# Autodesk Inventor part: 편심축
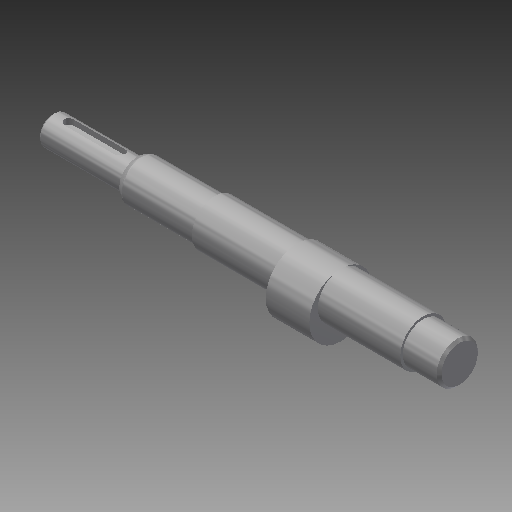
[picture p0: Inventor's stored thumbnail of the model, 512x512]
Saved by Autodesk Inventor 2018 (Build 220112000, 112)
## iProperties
Created: 2017-08
Part Number: 편심축
Material: 강철, 연강
Document SubType Name: Modeling
Designer: mduedu
Density: 1 g/cm^3
Appearance: 강철
Author: mduedu
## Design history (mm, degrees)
sketch "스케치1"
  geometry: L1 (0, 0)-(168, 0); L2 (168, 0)-(168, 8.5); L3 (168, 8.5)-(153, 8.5); L4 (153, 8.5)-(153, 9.5); L5 (153, 9.5)-(67, 9.5); L6 (67, 9.5)-(67, 8.5); L7 (67, 8.5)-(35, 8.5); L8 (35, 8.5)-(35, 6); L9 (35, 6)-(0, 6); L10 (0, 6)-(0, 0)
  constraints: 20 end point, 6 parallel, 2 collinear, 2 perpendicular, 1 horizontal
  dimensions: "d0" = 168 distance of L1.start L1.end; "d1" = 17 diameter of L3 L1; "d2" = 19 diameter of L5 L1; "d3" = 12 diameter of L9 L1; "d4" = 35 distance of L8.end L9.end; "d5" = 15 distance of L2.end L3.end; "d6" = 86 distance of L4.end L5.end
revolve "회전1" sketch "스케치1" stored, may be unused: angle "d7" = 90 deg
node "작업 평면1"
sketch "스케치2"
  geometry: C1 r 9.5 at (0, 0) reference; C2 r 13 at (0, -3.5); 1 further point
  constraints: 1 centre point, 1 tangent, 1 vertical alignment
  dimensions: "d8" = 3.5 distance of point (0, 0) C2.centre
extrude "돌출1" join sketch "스케치2" stored distance "d9" = 18; taper "d10" = 0 deg
chamfer "모따기1" distance "d11" = 1; stored, may be unused: second distance "d12" = 2, angle "d13" = 45 deg
node "작업 평면2"
sketch "스케치3"
  geometry: L1 (10.5, -2)-(-10.5, -2); L2 (-10.5, -2)-(-10.5, 2); L3 (-10.5, 2)-(10.5, 2); L4 (10.5, 2)-(10.5, -2); L5 (17.5, 6)-(17.5, -6) reference; L6 (-17.5, 8.5)-(-17.5, -8.5) reference; A1 r 2 centre (10.5, 0) between (10.5, -2) and (10.5, 2); A2 r 2 centre (-10.5, 0) between (-10.5, 2) and (-10.5, -2); A3 r 2 centre (10.5, 0) between (10.5, 2) and (10.5, -2); A4 r 2 centre (-10.5, 0) between (-10.5, -2) and (-10.5, 2); 1 further point
  constraints: 8 end point, 8 point on circle, 4 centre point, 2 midpoint, 2 parallel, 1 horizontal, 1 horizontal alignment, 1 perpendicular
  dimensions: "d14" = 25 dimension on A2 A1; "d16" = 4 distance between parallel lines of L3 L1; "d17" = 5 distance edge to line of A1 L5; "d46" = 5 distance edge to line of A2 L6 (derived)
extrude "돌출2" cut sketch "스케치3" distance "d18" = 2.5; taper "d19" = 0 deg
chamfer "모따기2" distance "d20" = 1; stored, may be unused: second distance "d21" = 2, angle "d22" = 45 deg
chamfer "모따기4" distance "d39" = 1.82; stored, may be unused: second distance "d40" = 2, angle "d41" = 30 deg
fillet "모깎기4" dims "d45" = 2
hole "구멍1" diameter "d29" = 3.242; stored, may be unused: countersink angle "d33" = 90 deg, drill point angle "d35" = 118 deg; dims "d30" = 8, "d31" = 4, "d32" = 2, "d34" = 10, "d36" = 10, "d37" = 10
node "솔리드1"
node "절단 모서리 투영1"
